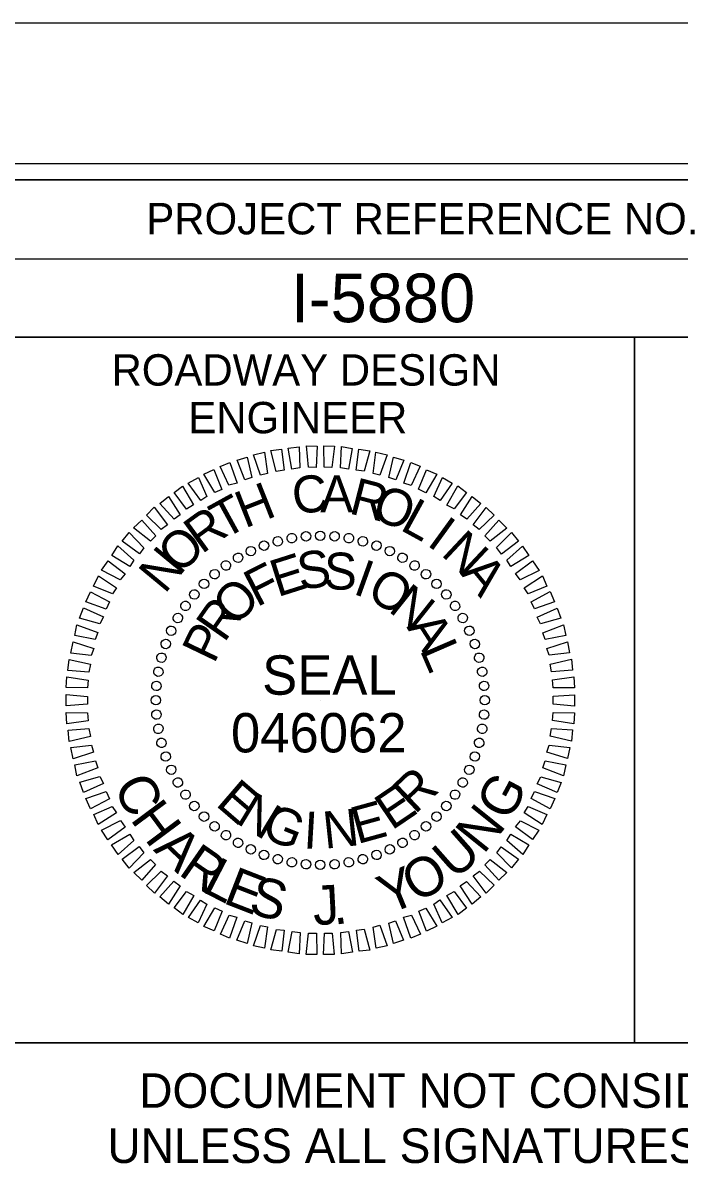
# Model space of a CAD drawing. Extents: x 1648435 to 1651603, y 802691 to 845762.
# Drawn here: x 1650331.8 to 1650436.5, y 803607.1 to 803791 of the extents above; entities that cross this region are included whole.
import ezdxf

# ---------------------------------------------------------------- set-up
doc = ezdxf.new("R2010")
doc.units = 0
for name, color, linetype in [('Default', 7, 'Continuous'), ('Old_Level_2', 7, 'Continuous'), ('Sheet Cutting Line CELL', 7, 'Continuous'), ('Sheet Data Field CELL', 7, 'Continuous'), ('Sheet Plot Border Inside CELL', 7, 'Continuous'), ('Sheet Plot Border Outside CELL', 7, 'Continuous'), ('Sheet Profile CELL', 7, 'Continuous'), ('Sheet Profile Grid Major CELL', 7, 'Continuous'), ('Sheet Profile Grid Minor CELL', 7, 'Continuous'), ('Sheet Sticker Exception Certification CELL', 7, 'Continuous')]:
    doc.layers.add(name, color=color, linetype=linetype)

msp = doc.modelspace()

# ---------------------------------------------------------------- linework, layer by layer
at = {"layer": 'Old_Level_2'}
for p, q in [((1650376.9, 803709.25), (1650376.9, 803709.25)), ((1650379.2, 803709.34), (1650379.2, 803709.34)), ((1650381.5, 803709.22), (1650381.5, 803709.22)), ((1650370.18, 803707.77), (1650370.18, 803707.77)), ((1650372.36, 803708.44), (1650372.36, 803708.44)), ((1650374.65, 803708.89), (1650374.65, 803708.89)), ((1650383.75, 803708.9), (1650383.75, 803708.9)), ((1650385.96, 803708.46), (1650385.96, 803708.46)), ((1650388.17, 803707.77), (1650388.17, 803707.77)), ((1650366.08, 803705.82), (1650366.08, 803705.82)), ((1650368.1, 803706.9), (1650368.1, 803706.9)), ((1650390.27, 803706.87), (1650390.27, 803706.87)), ((1650392.33, 803705.86), (1650392.33, 803705.86)), ((1650364.11, 803704.58), (1650364.11, 803704.58)), ((1650394.24, 803704.58), (1650394.24, 803704.58)), ((1650360.61, 803701.64), (1650360.61, 803701.64)), ((1650362.31, 803703.24), (1650362.31, 803703.24)), ((1650396.09, 803703.2), (1650396.09, 803703.2)), ((1650397.74, 803701.66), (1650397.74, 803701.66)), ((1650359.07, 803699.99), (1650359.07, 803699.99)), ((1650399.34, 803699.96), (1650399.34, 803699.96)), ((1650357.69, 803698.14), (1650357.69, 803698.14)), ((1650400.68, 803698.16), (1650400.68, 803698.16)), ((1650356.42, 803696.23), (1650356.42, 803696.23)), ((1650401.91, 803696.19), (1650401.91, 803696.19)), ((1650355.41, 803694.18), (1650355.41, 803694.18)), ((1650402.99, 803694.17), (1650402.99, 803694.17)), ((1650354.5, 803692.07), (1650354.5, 803692.07)), ((1650403.87, 803692.09), (1650403.87, 803692.09)), ((1650353.81, 803689.86), (1650353.81, 803689.86)), ((1650404.53, 803689.91), (1650404.53, 803689.91)), ((1650353.37, 803687.66), (1650353.37, 803687.66)), ((1650404.99, 803687.62), (1650404.99, 803687.62)), ((1650353.05, 803685.4), (1650353.05, 803685.4)), ((1650405.34, 803685.37), (1650405.34, 803685.37)), ((1650352.93, 803683.1), (1650352.93, 803683.1)), ((1650379.18, 803683.09), (1650379.18, 803683.09)), ((1650405.44, 803683.07), (1650405.44, 803683.07)), ((1650353.02, 803680.8), (1650353.02, 803680.8)), ((1650405.32, 803680.77), (1650405.32, 803680.77)), ((1650353.38, 803678.56), (1650353.38, 803678.56)), ((1650404.99, 803678.52), (1650404.99, 803678.52)), ((1650353.84, 803676.26), (1650353.84, 803676.26)), ((1650404.56, 803676.31), (1650404.56, 803676.31)), ((1650354.5, 803674.08), (1650354.5, 803674.08)), ((1650403.87, 803674.1), (1650403.87, 803674.1)), ((1650355.37, 803672), (1650355.37, 803672)), ((1650402.96, 803672), (1650402.96, 803672)), ((1650356.46, 803669.98), (1650356.46, 803669.98)), ((1650401.95, 803669.94), (1650401.95, 803669.94)), ((1650357.69, 803668.02), (1650357.69, 803668.02)), ((1650400.68, 803668.03), (1650400.68, 803668.03)), ((1650359.03, 803666.21), (1650359.03, 803666.21)), ((1650399.3, 803666.18), (1650399.3, 803666.18)), ((1650360.63, 803664.51), (1650360.63, 803664.51)), ((1650397.76, 803664.53), (1650397.76, 803664.53)), ((1650362.28, 803662.97), (1650362.28, 803662.97)), ((1650364.13, 803661.59), (1650364.13, 803661.59)), ((1650394.25, 803661.59), (1650394.25, 803661.59)), ((1650396.06, 803662.93), (1650396.06, 803662.93)), ((1650366.04, 803660.32), (1650366.04, 803660.32)), ((1650368.09, 803659.31), (1650368.09, 803659.31)), ((1650392.29, 803660.36), (1650392.29, 803660.36)), ((1650370.2, 803658.4), (1650370.2, 803658.4)), ((1650372.41, 803657.71), (1650372.41, 803657.71)), ((1650386.01, 803657.74), (1650386.01, 803657.74)), ((1650388.19, 803658.4), (1650388.19, 803658.4)), ((1650390.27, 803659.28), (1650390.27, 803659.28)), ((1650374.61, 803657.28), (1650374.61, 803657.28)), ((1650376.87, 803656.95), (1650376.87, 803656.95)), ((1650379.17, 803656.83), (1650379.17, 803656.83)), ((1650381.47, 803656.93), (1650381.47, 803656.93)), ((1650383.71, 803657.28), (1650383.71, 803657.28))]:
    msp.add_line(p, q, dxfattribs=at)
for points in [[(1650367.17, 803718.23), (1650365.91, 803721.34), (1650367.53, 803721.84), (1650368.26, 803718.61)], [(1650369.67, 803718.95), (1650368.51, 803722.23), (1650370.28, 803722.62), (1650370.76, 803719.23)], [(1650372.17, 803719.57), (1650371.27, 803722.9), (1650373, 803723.09), (1650373.42, 803719.75)], [(1650374.67, 803719.93), (1650374.04, 803723.26), (1650375.81, 803723.5), (1650375.92, 803720.11)], [(1650377.28, 803720.24), (1650376.96, 803723.63), (1650378.69, 803723.61), (1650378.54, 803720.21)], [(1650379.79, 803720.23), (1650379.73, 803723.63), (1650381.46, 803723.6), (1650381.05, 803720.2)], [(1650382.41, 803720.12), (1650382.56, 803723.52), (1650384.29, 803723.23), (1650383.67, 803719.93)], [(1650384.92, 803719.74), (1650385.34, 803723.1), (1650387.07, 803722.86), (1650386.18, 803719.61)], [(1650387.6, 803719.21), (1650388.06, 803722.62), (1650389.85, 803722.23), (1650388.7, 803718.97)], [(1650364.62, 803717.35), (1650363.21, 803720.36), (1650364.77, 803721.01), (1650365.92, 803717.68)], [(1650390.12, 803718.58), (1650390.85, 803721.83), (1650392.48, 803721.34), (1650391.23, 803718.23)], [(1650392.49, 803717.68), (1650393.64, 803720.99), (1650395.11, 803720.39), (1650393.7, 803717.33)], [(1650360.12, 803714.92), (1650358.13, 803717.71), (1650359.74, 803718.57), (1650361.1, 803715.56)], [(1650362.34, 803716.21), (1650360.62, 803719.11), (1650362.23, 803719.87), (1650363.48, 803716.7)], [(1650394.86, 803716.72), (1650396.11, 803719.83), (1650397.75, 803719.13), (1650396.02, 803716.17)], [(1650397.29, 803715.56), (1650398.65, 803718.57), (1650400.23, 803717.71), (1650398.29, 803714.95)], [(1650357.84, 803713.57), (1650355.86, 803716.2), (1650357.2, 803717.22), (1650358.98, 803714.22)], [(1650399.35, 803714.19), (1650401.13, 803717.25), (1650402.51, 803716.18), (1650400.51, 803713.58)], [(1650355.88, 803711.97), (1650353.59, 803714.44), (1650354.98, 803715.56), (1650356.86, 803712.66)], [(1650401.52, 803712.66), (1650403.41, 803715.57), (1650404.79, 803714.44), (1650402.53, 803711.94)], [(1650353.82, 803710.31), (1650351.48, 803712.57), (1650352.71, 803713.85), (1650354.8, 803711.06)], [(1650403.54, 803711.07), (1650405.63, 803713.83), (1650406.91, 803712.59), (1650404.54, 803710.3)], [(1650352.12, 803708.45), (1650349.42, 803710.55), (1650350.71, 803711.77), (1650352.94, 803709.3)], [(1650405.45, 803709.27), (1650407.66, 803711.77), (1650408.93, 803710.54), (1650406.25, 803708.45)], [(1650350.33, 803706.43), (1650347.57, 803708.42), (1650348.7, 803709.8), (1650351.04, 803707.38)], [(1650407.31, 803707.42), (1650409.68, 803709.82), (1650410.8, 803708.43), (1650408.06, 803706.39)], [(1650348.79, 803704.42), (1650345.94, 803706.14), (1650346.91, 803707.68), (1650349.46, 803705.42)], [(1650408.92, 803705.41), (1650411.44, 803707.65), (1650412.46, 803706.15), (1650409.56, 803704.43)], [(1650347.26, 803702.3), (1650344.31, 803703.81), (1650345.33, 803705.3), (1650348.08, 803703.25)], [(1650410.31, 803703.29), (1650413.05, 803705.33), (1650414.07, 803703.78), (1650411.06, 803702.26)], [(1650346.05, 803700.03), (1650343.04, 803701.28), (1650343.8, 803702.92), (1650346.66, 803701.03)], [(1650411.71, 803701.02), (1650414.61, 803702.9), (1650415.32, 803701.29), (1650412.36, 803700.03)], [(1650345.04, 803697.6), (1650341.78, 803698.75), (1650342.54, 803700.38), (1650345.55, 803698.76)], [(1650412.8, 803698.79), (1650415.86, 803700.41), (1650416.56, 803698.75), (1650413.34, 803697.65)], [(1650344.04, 803695.29), (1650340.78, 803696.17), (1650341.43, 803697.8), (1650344.59, 803696.39)], [(1650413.78, 803696.35), (1650416.95, 803697.76), (1650417.55, 803696.15), (1650414.32, 803695.26)], [(1650343.3, 803692.76), (1650340.04, 803693.39), (1650340.38, 803695.12), (1650343.7, 803693.87)], [(1650414.66, 803693.85), (1650417.99, 803695.11), (1650418.33, 803693.39), (1650415.05, 803692.76)], [(1650342.66, 803690.24), (1650339.41, 803690.6), (1650339.75, 803692.39), (1650343.06, 803691.35)], [(1650415.33, 803691.35), (1650418.61, 803692.4), (1650418.95, 803690.63), (1650415.67, 803690.26)], [(1650342.29, 803687.57), (1650338.94, 803687.82), (1650339.12, 803689.6), (1650342.53, 803688.83)], [(1650415.85, 803688.85), (1650419.23, 803689.64), (1650419.42, 803687.87), (1650416.08, 803687.6)], [(1650342.07, 803685.05), (1650338.67, 803685.1), (1650338.75, 803686.83), (1650342.15, 803686.31)], [(1650416.21, 803686.35), (1650419.6, 803686.82), (1650419.73, 803685.05), (1650416.33, 803685.09)], [(1650342.07, 803682.44), (1650338.67, 803682.22), (1650338.64, 803684), (1650342.04, 803683.69)], [(1650416.3, 803683.73), (1650419.7, 803683.95), (1650419.73, 803682.17), (1650416.33, 803682.48)], [(1650342.16, 803679.83), (1650338.77, 803679.35), (1650338.64, 803681.12), (1650342.04, 803681.08)], [(1650416.3, 803681.12), (1650419.7, 803681.07), (1650419.62, 803679.35), (1650416.21, 803679.86)], [(1650342.52, 803677.32), (1650339.14, 803676.53), (1650338.95, 803678.3), (1650342.29, 803678.57)], [(1650416.08, 803678.61), (1650419.43, 803678.35), (1650419.25, 803676.57), (1650415.84, 803677.35)], [(1650343.04, 803674.82), (1650339.76, 803673.77), (1650339.41, 803675.54), (1650342.7, 803675.91)], [(1650415.71, 803675.93), (1650418.96, 803675.57), (1650418.62, 803673.79), (1650415.31, 803674.83)], [(1650343.71, 803672.32), (1650340.38, 803671.06), (1650340.04, 803672.78), (1650343.32, 803673.41)], [(1650415.07, 803673.41), (1650418.32, 803672.79), (1650417.99, 803671.06), (1650414.67, 803672.31)], [(1650344.59, 803669.83), (1650341.42, 803668.41), (1650340.82, 803670.02), (1650344.04, 803670.92)], [(1650414.33, 803670.89), (1650417.59, 803670), (1650416.94, 803668.37), (1650413.78, 803669.78)], [(1650345.57, 803667.39), (1650342.51, 803665.76), (1650341.8, 803667.42), (1650345.03, 803668.53)], [(1650413.33, 803668.57), (1650416.59, 803667.42), (1650415.83, 803665.79), (1650412.82, 803667.41)], [(1650346.66, 803665.16), (1650343.76, 803663.28), (1650343.05, 803664.88), (1650346.01, 803666.14)], [(1650412.32, 803666.15), (1650415.33, 803664.89), (1650414.57, 803663.26), (1650411.71, 803665.14)], [(1650348.05, 803662.88), (1650345.32, 803660.84), (1650344.3, 803662.4), (1650347.3, 803663.91)], [(1650411.11, 803663.88), (1650414.06, 803662.36), (1650413.04, 803660.88), (1650410.29, 803662.92)], [(1650349.45, 803660.76), (1650346.93, 803658.52), (1650345.91, 803660.02), (1650348.81, 803661.74)], [(1650409.57, 803661.76), (1650412.43, 803660.03), (1650411.46, 803658.5), (1650408.91, 803660.75)], [(1650351.06, 803658.75), (1650348.69, 803656.35), (1650347.57, 803657.75), (1650350.31, 803659.78)], [(1650408.04, 803659.74), (1650410.8, 803657.75), (1650409.67, 803656.37), (1650407.33, 803658.79)], [(1650352.92, 803656.9), (1650350.71, 803654.4), (1650349.44, 803655.63), (1650352.12, 803657.72)], [(1650406.25, 803657.72), (1650408.95, 803655.63), (1650407.66, 803654.4), (1650405.42, 803656.87)], [(1650354.83, 803655.1), (1650352.74, 803652.35), (1650351.46, 803653.58), (1650353.83, 803655.87)], [(1650404.55, 803655.86), (1650406.89, 803653.6), (1650405.66, 803652.33), (1650403.57, 803655.12)], [(1650356.85, 803653.52), (1650354.96, 803650.61), (1650353.58, 803651.73), (1650355.84, 803654.23)], [(1650402.49, 803654.21), (1650404.78, 803651.74), (1650403.39, 803650.61), (1650401.51, 803653.51)], [(1650359.02, 803651.98), (1650357.24, 803648.92), (1650355.86, 803649.99), (1650357.86, 803652.59)], [(1650400.53, 803652.6), (1650402.51, 803649.97), (1650401.17, 803648.95), (1650399.39, 803651.96)], [(1650361.08, 803650.61), (1650359.72, 803647.6), (1650358.14, 803648.46), (1650360.08, 803651.22)], [(1650398.25, 803651.26), (1650400.24, 803648.47), (1650398.63, 803647.6), (1650397.27, 803650.61)], [(1650363.51, 803649.45), (1650362.25, 803646.34), (1650360.62, 803647.04), (1650362.35, 803650)], [(1650365.88, 803648.5), (1650364.73, 803645.18), (1650363.26, 803645.78), (1650364.67, 803648.84)], [(1650393.75, 803648.82), (1650395.16, 803645.82), (1650393.6, 803645.16), (1650392.44, 803648.49)], [(1650396.03, 803649.96), (1650397.75, 803647.06), (1650396.14, 803646.3), (1650394.88, 803649.47)], [(1650368.25, 803647.6), (1650367.52, 803644.34), (1650365.89, 803644.83), (1650367.14, 803647.94)], [(1650370.77, 803646.96), (1650370.3, 803643.55), (1650368.52, 803643.94), (1650369.67, 803647.2)], [(1650373.44, 803646.43), (1650373.03, 803643.08), (1650371.3, 803643.31), (1650372.19, 803646.57)], [(1650386.2, 803646.6), (1650387.1, 803643.27), (1650385.37, 803643.08), (1650384.95, 803646.42)], [(1650388.7, 803647.22), (1650389.86, 803643.95), (1650388.09, 803643.55), (1650387.61, 803646.94)], [(1650391.2, 803647.94), (1650392.46, 803644.83), (1650390.84, 803644.33), (1650390.11, 803647.56)], [(1650375.96, 803646.06), (1650375.81, 803642.65), (1650374.08, 803642.94), (1650374.7, 803646.24)], [(1650378.58, 803645.95), (1650378.64, 803642.55), (1650376.91, 803642.57), (1650377.32, 803645.98)], [(1650381.09, 803645.94), (1650381.41, 803642.54), (1650379.68, 803642.57), (1650379.83, 803645.97)], [(1650383.7, 803646.24), (1650384.33, 803642.91), (1650382.56, 803642.67), (1650382.45, 803646.07)]]:
    msp.add_lwpolyline(points, close=True, dxfattribs=at)
for centre, major_axis in [((1650372.4, 803708.42), (-0.195, 0.727)), ((1650374.63, 803708.92), (-0.131, 0.742)), ((1650376.9, 803709.21), (-0.066, 0.75)), ((1650379.18, 803709.31), (0, 0.753)), ((1650381.47, 803709.21), (0.066, 0.75)), ((1650383.74, 803708.92), (0.131, 0.742)), ((1650385.97, 803708.42), (0.195, 0.727)), ((1650368.1, 803706.86), (-0.318, 0.682)), ((1650370.21, 803707.73), (-0.258, 0.708)), ((1650388.15, 803707.73), (0.258, 0.708)), ((1650390.27, 803706.86), (0.318, 0.682)), ((1650364.14, 803704.57), (-0.432, 0.617)), ((1650366.07, 803705.8), (-0.376, 0.652)), ((1650392.3, 803705.8), (0.376, 0.652)), ((1650394.23, 803704.57), (0.432, 0.617)), ((1650362.33, 803703.18), (-0.484, 0.577)), ((1650396.04, 803703.18), (0.484, 0.577)), ((1650360.64, 803701.63), (-0.532, 0.532)), ((1650397.73, 803701.63), (0.532, 0.532)), ((1650359.09, 803699.95), (-0.577, 0.484)), ((1650399.28, 803699.95), (0.577, 0.484)), ((1650357.7, 803698.13), (-0.617, 0.432)), ((1650400.67, 803698.13), (0.617, 0.432)), ((1650356.47, 803696.2), (-0.652, 0.376)), ((1650401.9, 803696.2), (0.652, 0.376)), ((1650355.41, 803694.17), (-0.682, 0.318)), ((1650402.95, 803694.17), (0.682, 0.318)), ((1650354.54, 803692.06), (-0.708, 0.258)), ((1650403.83, 803692.06), (0.708, 0.258)), ((1650353.85, 803689.87), (-0.727, 0.195)), ((1650404.52, 803689.87), (0.727, 0.195)), ((1650353.36, 803687.64), (-0.742, 0.131)), ((1650405.01, 803687.64), (0.742, 0.131)), ((1650353.06, 803685.37), (-0.75, 0.066)), ((1650405.31, 803685.37), (0.75, 0.066)), ((1650352.96, 803683.09), (-0.753, 0)), ((1650405.41, 803683.09), (0.753, 0)), ((1650353.06, 803680.8), (-0.75, -0.066)), ((1650405.31, 803680.8), (0.75, -0.066)), ((1650353.36, 803678.53), (-0.742, -0.131)), ((1650405.01, 803678.53), (0.742, -0.131)), ((1650353.85, 803676.3), (-0.727, -0.195)), ((1650404.52, 803676.3), (0.727, -0.195)), ((1650354.54, 803674.12), (-0.708, -0.258)), ((1650403.83, 803674.12), (0.708, -0.258)), ((1650355.41, 803672), (-0.682, -0.318)), ((1650402.95, 803672), (0.682, -0.318)), ((1650356.47, 803669.97), (-0.652, -0.376)), ((1650401.9, 803669.97), (0.652, -0.376)), ((1650357.7, 803668.04), (-0.617, -0.432)), ((1650400.67, 803668.04), (0.617, -0.432)), ((1650359.09, 803666.23), (-0.577, -0.484)), ((1650399.28, 803666.23), (0.577, -0.484)), ((1650360.64, 803664.54), (-0.532, -0.532)), ((1650397.73, 803664.54), (0.532, -0.532)), ((1650362.33, 803662.99), (-0.484, -0.577)), ((1650396.04, 803662.99), (0.484, -0.577)), ((1650364.14, 803661.6), (-0.432, -0.617)), ((1650366.07, 803660.37), (-0.376, -0.652)), ((1650392.3, 803660.37), (0.376, -0.652)), ((1650394.23, 803661.6), (0.432, -0.617)), ((1650368.1, 803659.32), (-0.318, -0.682)), ((1650390.27, 803659.32), (0.318, -0.682)), ((1650370.21, 803658.44), (-0.258, -0.708)), ((1650372.4, 803657.75), (-0.195, -0.727)), ((1650374.63, 803657.26), (-0.131, -0.742)), ((1650376.9, 803656.96), (-0.066, -0.75)), ((1650379.18, 803656.86), (0, -0.753)), ((1650381.47, 803656.96), (0.066, -0.75)), ((1650383.74, 803657.26), (0.131, -0.742)), ((1650385.97, 803657.75), (0.195, -0.727)), ((1650388.15, 803658.44), (0.258, -0.708))]:
    msp.add_ellipse(centre, major_axis=major_axis, ratio=0.999708, dxfattribs=at)
at = {"layer": 'Sheet Cutting Line CELL'}
msp.add_line((1650546.28, 803791.02), (1648862.28, 803791.02), dxfattribs=at)
at = {"layer": 'Sheet Plot Border Inside CELL'}
msp.add_lwpolyline([(1648875.28, 802713.47), (1650541.78, 802713.47), (1650541.78, 803768.57), (1648875.28, 803768.57)], close=True, dxfattribs=at)
at = {"layer": 'Sheet Plot Border Outside CELL'}
msp.add_lwpolyline([(1648862.28, 802691.02), (1650546.28, 802691.02), (1650546.28, 803791.02), (1648862.28, 803791.02)], close=True, dxfattribs=at)
at = {"layer": 'Sheet Profile CELL'}
for p, q in [((1650329.23, 803753.47), (1650529.28, 803753.47)), ((1650429.28, 803740.97), (1650429.28, 803628.52))]:
    msp.add_line(p, q, dxfattribs=at)
for points in [[(1650529.28, 803766.02), (1649029.28, 803766.02), (1649029.28, 802716.02), (1650529.28, 802716.02)], [(1650329.23, 803766.02), (1650529.28, 803766.02), (1650529.28, 803740.97), (1650329.23, 803740.97)], [(1650329.23, 803740.97), (1650429.28, 803740.97), (1650429.28, 803628.47), (1650329.23, 803628.47)], [(1650429.28, 803740.97), (1650529.28, 803740.97), (1650529.28, 803628.47), (1650429.28, 803628.47)]]:
    msp.add_lwpolyline(points, close=True, dxfattribs=at)
at = {"layer": 'Sheet Profile Grid Major CELL'}
msp.add_lwpolyline([(1650279.23, 803738.96), (1650279.23, 803266.02), (1650329.23, 803266.02), (1650329.23, 803766.02), (1650355.53, 803766.02)], dxfattribs=at)
at = {"layer": 'Sheet Profile Grid Minor CELL'}
msp.add_lwpolyline([(1650324.28, 803766.02), (1650334.28, 803766.02)], dxfattribs=at)
at = {"layer": 'Sheet Sticker Exception Certification CELL'}
msp.add_line((1650329.23, 803628.47), (1650529.27, 803628.47), dxfattribs=at)
msp.add_line((1650329.23, 803628.47), (1650529.27, 803628.47), dxfattribs=at)

# ---------------------------------------------------------------- texts
at = {"layer": 'Default'}
for s, rotation, p in [('C', 297.1999, (1650346.07, 803669.36)), ('G', 61.7998, (1650409.3, 803663.59)), ('H', 306.6436, (1650348.76, 803664.11)), ('N', 51.2288, (1650405.21, 803658.4)), ('A', 316.4834, (1650352.45, 803659.18)), ('U', 41.4347, (1650400.63, 803654.33)), ('R', 325.1961, (1650356.38, 803655.41)), ('L', 332.5683, (1650360.12, 803652.71)), ('O', 30.0413, (1650394.53, 803650.66)), ('E', 338.7525, (1650363.5, 803650.83)), ('Y', 22.2426, (1650390, 803648.88)), ('S', 345.7591, (1650367.55, 803649.16)), ('J', 3.0321, (1650378.14, 803647.23)), ('.', 8.214, (1650381.39, 803647.28))]:
    msp.add_text(s, height=6.27, rotation=rotation, dxfattribs=at).set_placement(p)
at = {"layer": 'Old_Level_2'}
for s, rotation, p in [('C', 7.2199, (1650375.06, 803712.67)), ('A', 0.0203, (1650379.18, 803713.05)), ('R', 345.6211, (1650383.58, 803712.92)), ('H', 21.6195, (1650367.15, 803710.44)), ('O', 338.4212, (1650387.1, 803712.2)), ('T', 28.8198, (1650363.78, 803708.65)), ('L', 331.2209, (1650391.73, 803710.34)), ('R', 36.0205, (1650360.27, 803706.29)), ('I', 324.0201, (1650396.01, 803707.91)), ('O', 43.2217, (1650356.72, 803702.99)), ('N', 316.8189, (1650398.29, 803706.33)), ('N', 50.4235, (1650354.36, 803699.91)), ('E', 17.6111, (1650372.36, 803699.49)), ('S', 8.2556, (1650375.95, 803700.65)), ('S', 358.9004, (1650379.71, 803700.77)), ('I', 340.1896, (1650384.22, 803700.12)), ('A', 309.6172, (1650401.42, 803703.29)), ('F', 26.967, (1650369.04, 803697.87)), ('O', 330.8335, (1650386.33, 803699.42)), ('O', 45.6812, (1650365.65, 803694.72)), ('N', 321.4766, (1650389.86, 803697.39)), ('R', 55.0397, (1650363.86, 803692.13)), ('P', 64.3989, (1650362.25, 803688.75)), ('A', 302.7603, (1650392.89, 803694.73)), ('L', 293.4009, (1650394.99, 803691.15)), ('E', 319.2769, (1650362.32, 803666.42)), ('R', 43.4814, (1650394.25, 803664.78)), ('E', 34.1241, (1650390.58, 803662.26)), ('N', 328.634, (1650365.51, 803663.65)), ('E', 15.4118, (1650385.08, 803660.13)), ('G', 337.9902, (1650369.52, 803661.37)), ('I', 356.7012, (1650376.41, 803659.5)), ('N', 6.0564, (1650379.91, 803659.41))]:
    msp.add_text(s, height=5.9, rotation=rotation, dxfattribs=at).set_placement(p)
for s, height, p in [('SEAL', 6.273, (1650369.91, 803683.97)), ('046062', 6.275, (1650364.94, 803674.77))]:
    msp.add_text(s, height=height, dxfattribs=at).set_placement(p)
at = {"layer": 'Sheet Data Field CELL'}
msp.add_text('I-5880', height=7.75, dxfattribs=at).set_placement((1650374.49, 803743.34))
at = {"layer": 'Sheet Profile CELL'}
for s, height, p in [('PROJECT REFERENCE NO.', 5.0001, (1650351.44, 803757.34)), ('ROADWAY DESIGN', 5.0001, (1650345.89, 803733.24)), ('ENGINEER', 5, (1650358.14, 803725.64))]:
    msp.add_text(s, height=height, dxfattribs=at).set_placement(p)
at = {"layer": 'Sheet Sticker Exception Certification CELL'}
for s, p in [('DOCUMENT NOT CONSIDERED FINAL', (1650350.3, 803618.13)), ('DOCUMENT NOT CONSIDERED FINAL', (1650350.3, 803618.13)), ('UNLESS ALL SIGNATURES COMPLETED', (1650345.23, 803609.33)), ('UNLESS ALL SIGNATURES COMPLETED', (1650345.23, 803609.33))]:
    msp.add_text(s, height=5.5, dxfattribs=at).set_placement(p)

doc.saveas('drawing.dxf')
